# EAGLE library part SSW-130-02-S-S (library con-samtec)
THROUGH-HOLE .025" SQ POST SOCKET Source: Samtec SSW.pdf
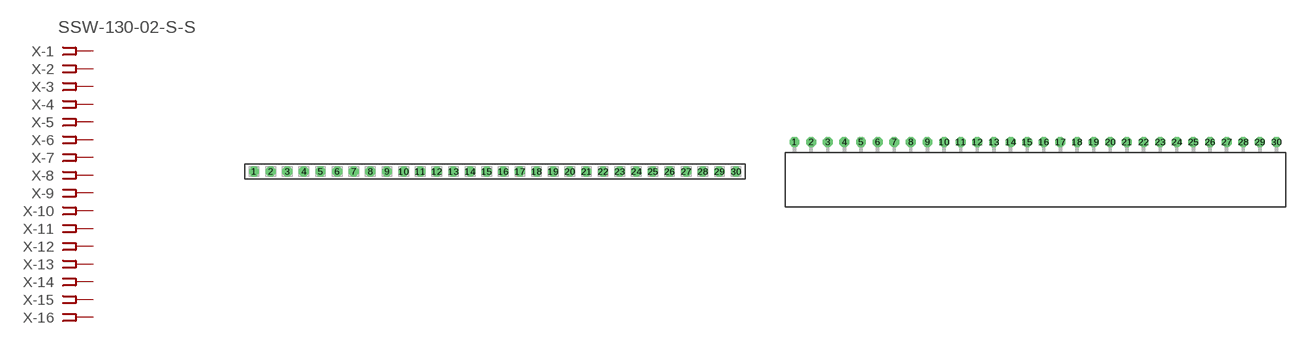
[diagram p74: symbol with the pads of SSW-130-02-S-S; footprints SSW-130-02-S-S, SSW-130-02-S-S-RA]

Designator prefix X; gates -1=FPINV -2=FPIN -3=FPIN -4=FPIN -5=FPIN -6=FPIN -7=FPIN -8=FPIN -9=FPIN -10=FPIN -11=FPIN -12=FPIN -13=FPIN -14=FPIN -15=FPIN -16=FPIN -17=FPIN -18=FPIN -19=FPIN -20=FPIN -21=FPIN -22=FPIN -23=FPIN -24=FPIN -25=FPIN -26=FPIN -27=FPIN -28=FPIN -29=FPIN -30=FPIN

## SSW-130-02-S-S (MPN: SSW-130-02-S-S; OC_FARNELL: unknown; OC_NEWARK: 11P9806)  [SSW-130-02-S-S]
1  -1:1  pas
2  -2:1  pas
3  -3:1  pas
4  -4:1  pas
5  -5:1  pas
6  -6:1  pas
7  -7:1  pas
8  -8:1  pas
9  -9:1  pas
10  -10:1  pas
11  -11:1  pas
12  -12:1  pas
13  -13:1  pas
14  -14:1  pas
15  -15:1  pas
16  -16:1  pas
17  -17:1  pas
18  -18:1  pas
19  -19:1  pas
20  -20:1  pas
21  -21:1  pas
22  -22:1  pas
23  -23:1  pas
24  -24:1  pas
25  -25:1  pas
26  -26:1  pas
27  -27:1  pas
28  -28:1  pas
29  -29:1  pas
30  -30:1  pas

## SSW-130-02-S-S-RA (MPN: SSW-130-02-S-S-RA; OC_FARNELL: unknown; OC_NEWARK: 11P9807)  [SSW-130-02-S-S-RA]
Pads as for SSW-130-02-S-S

## Footprint SSW-130-02-S-S (pad centres in mm)
THROUGH-HOLE .025" SQ POST SOCKET Source: Samtec SSW.pdf
drill 1 pad 1.5 octagon: 1 -36.83,0; 2 -34.29,0; 3 -31.75,0; 4 -29.21,0; 5 -26.67,0; 6 -24.13,0; 7 -21.59,0; 8 -19.05,0; 9 -16.51,0; 10 -13.97,0; 11 -11.43,0; 12 -8.89,0; 13 -6.35,0; 14 -3.81,0; 15 -1.27,0; 16 1.27,0; 17 3.81,0; 18 6.35,0; 19 8.89,0; 20 11.43,0; 21 13.97,0; 22 16.51,0; 23 19.05,0; 24 21.59,0; 25 24.13,0; 26 26.67,0; 27 29.21,0; 28 31.75,0; 29 34.29,0; 30 36.83,0

## Footprint SSW-130-02-S-S-RA (pad centres in mm)
THROUGH-HOLE .025" SQ POST SOCKET Source: Samtec SSW.pdf
drill 1 pad 1.5 octagon: 1 -36.83,1.524; 2 -34.29,1.524; 3 -31.75,1.524; 4 -29.21,1.524; 5 -26.67,1.524; 6 -24.13,1.524; 7 -21.59,1.524; 8 -19.05,1.524; 9 -16.51,1.524; 10 -13.97,1.524; 11 -11.43,1.524; 12 -8.89,1.524; 13 -6.35,1.524; 14 -3.81,1.524; 15 -1.27,1.524; 16 1.27,1.524; 17 3.81,1.524; 18 6.35,1.524; 19 8.89,1.524; 20 11.43,1.524; 21 13.97,1.524; 22 16.51,1.524; 23 19.05,1.524; 24 21.59,1.524; 25 24.13,1.524; 26 26.67,1.524; 27 29.21,1.524; 28 31.75,1.524; 29 34.29,1.524; 30 36.83,1.524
